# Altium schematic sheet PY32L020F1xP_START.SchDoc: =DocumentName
size A3; Revision: V2.0; SheetNumber: 2; SheetTotal: 2
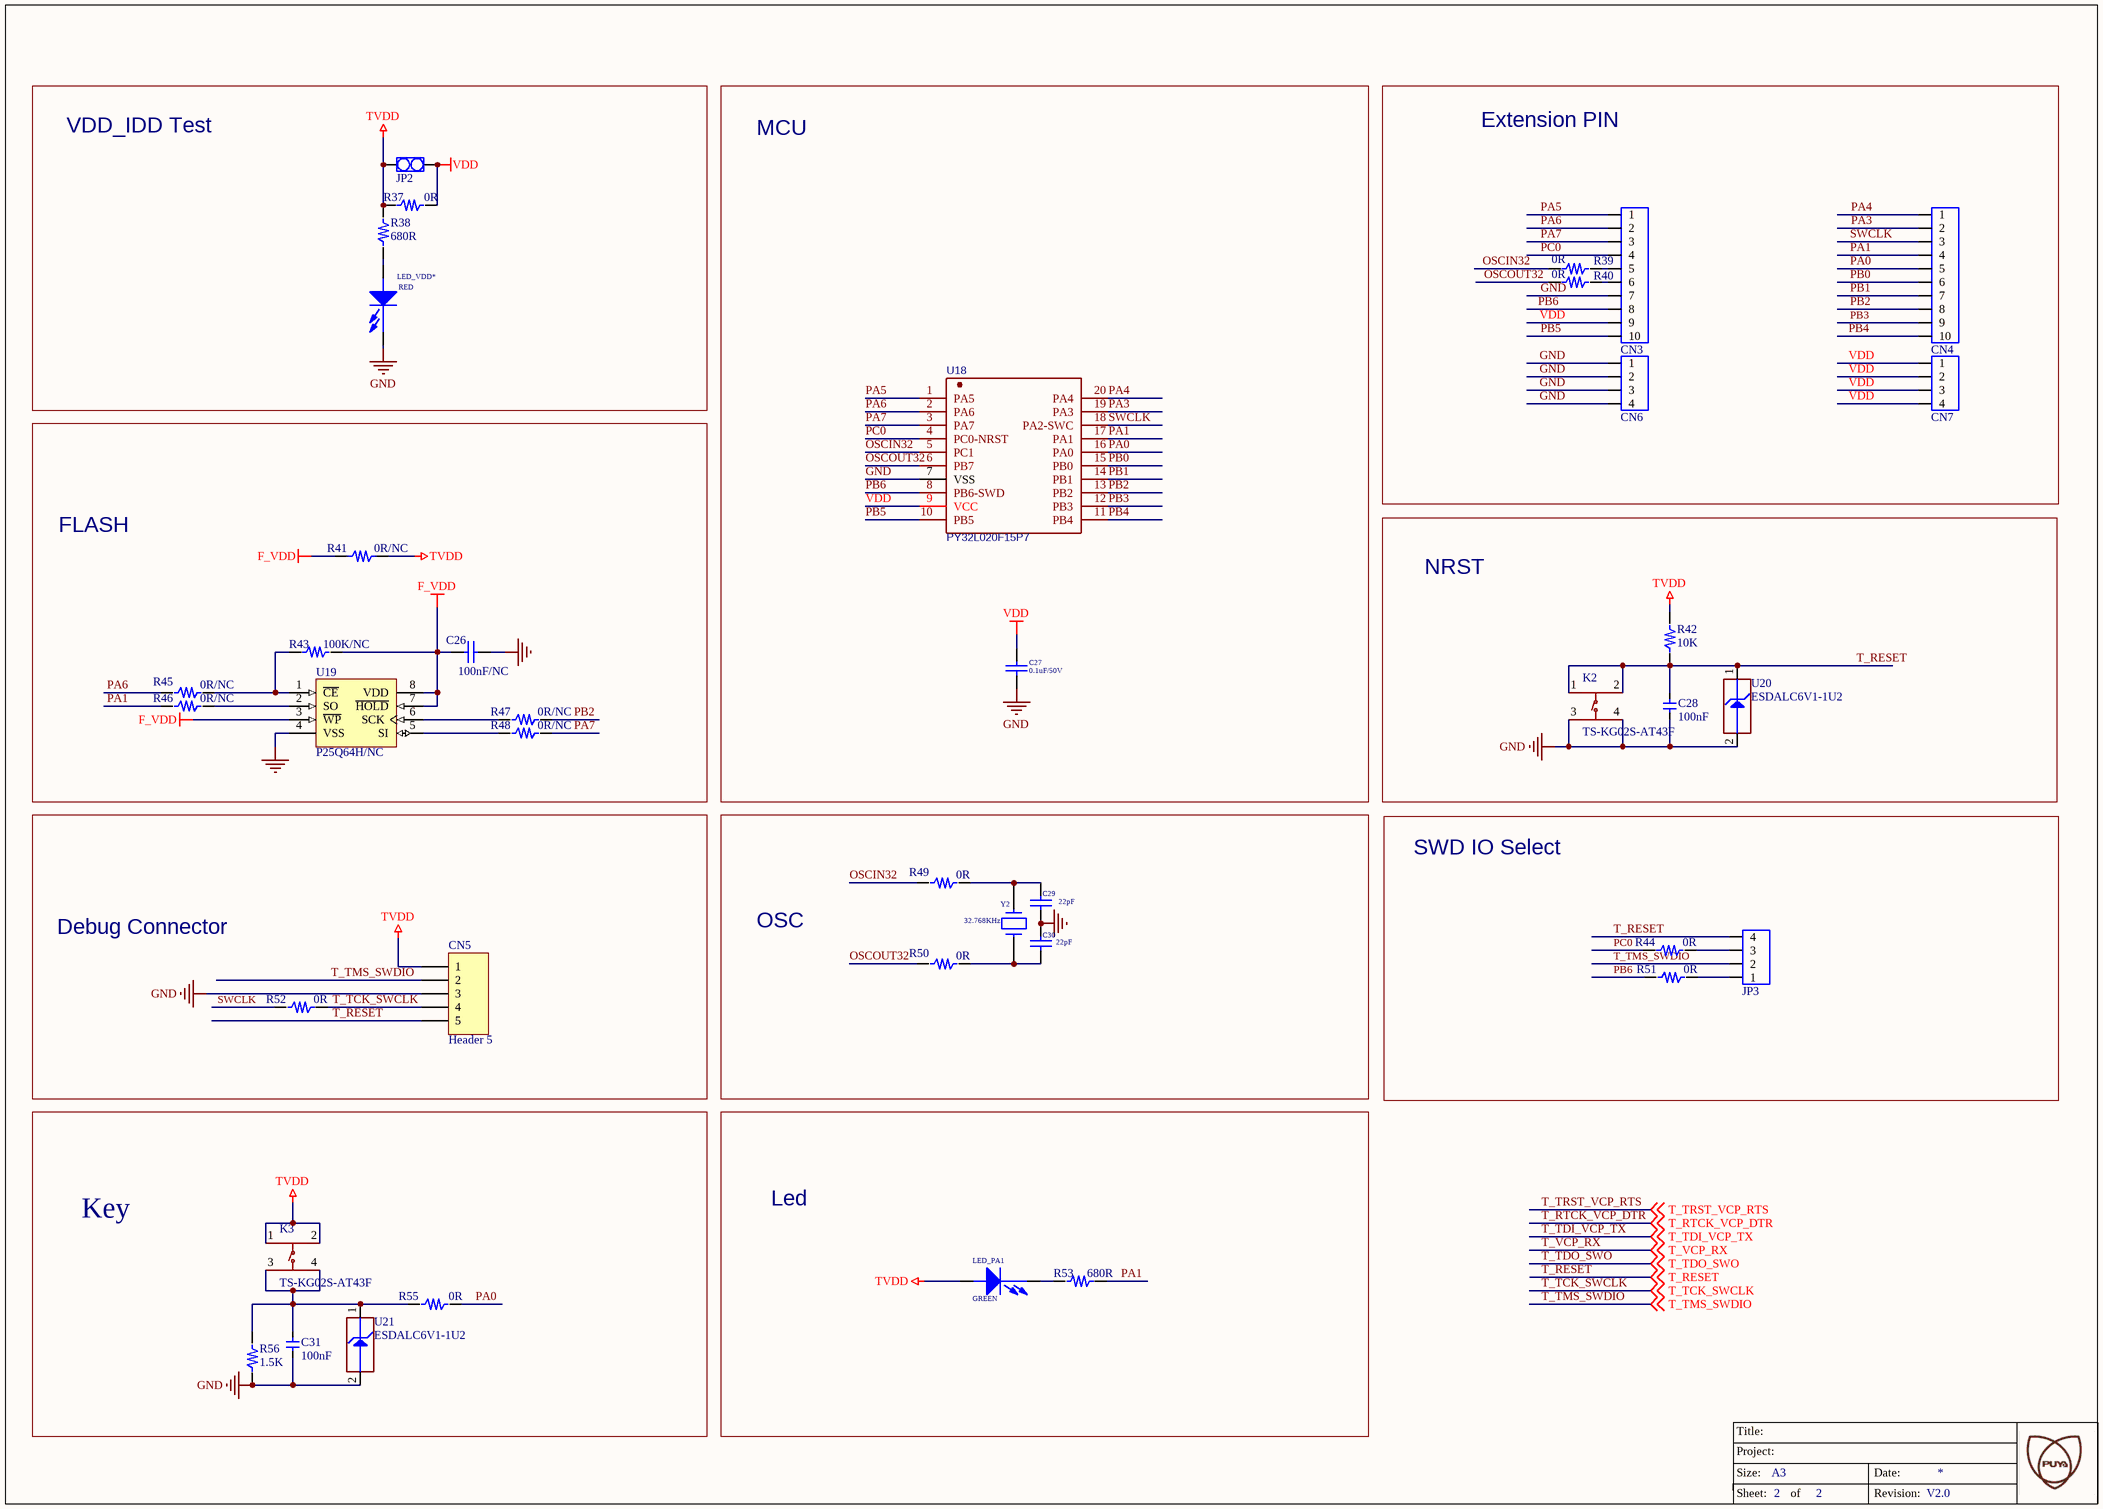
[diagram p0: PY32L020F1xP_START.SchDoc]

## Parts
C26  100nF/NC  [C0603]
C27  0.1uF/50V  [0603C]
C28  100nF  [C0603]
C29  22pF  [0603C]
C30  22pF  [0603C]
C31  100nF  [C0603]
CN3  CON10  [CON10]  (value not drawn)
CN4  CON10  [CON10]  (value not drawn)
CN5  Header 5  [HDR1X5]
CN6  CON4  [CON4]  (value not drawn)
CN7  CON4  [CON4]  (value not drawn)
JP2  CON2  [CON2]  (value not drawn)
JP3  CON4  [CON4]  (value not drawn)
K2  TS-KG02S-AT43F  [SW-SMD_4P-L6.0-W6.0-P4.50-LS8.5]
K3  TS-KG02S-AT43F  [SW-SMD_4P-L6.0-W6.0-P4.50-LS8.5]
LED_PA1  GREEN  [0603_LED]
LED_VDD*  RED  [0603_LED]
R37  0R  [JP2_SMD]
R38  680R  [R0603]
R39  0R  [JP2_SMD]
R40  0R  [JP2_SMD]
R41  0R/NC  [JP2_SMD]
R42  10K  [R0603]
R43  100K/NC  [R0603]
R44  0R  [JP2_SMD]
R45  0R/NC  [JP2_SMD]
R46  0R/NC  [JP2_SMD]
R47  0R/NC  [JP2_SMD]
R48  0R/NC  [JP2_SMD]
R49  0R  [JP2_SMD]
R50  0R  [JP2_SMD]
R51  0R  [JP2_SMD]
R52  0R  [JP2_SMD]
R53  680R  [R0603]
R55  0R  [JP2_SMD]
R56  1.5K  [R0603]
U18  PY32L020F15P7  [TSSOP-20_L6.5-W4.4-P0.65-LS6.4-BL]
U19  P25Q64H/NC  [SOP-8P]
U20  ESDALC6V1-1U2  [ESD_ST0201]
U21  ESDALC6V1-1U2  [ESD_ST0201]
Y2  32.768KHz  [CRYSTAL-SMD_L3.2-W1.5-1]

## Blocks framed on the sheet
VDD_IDD Test: JP2 LED_VDD* R37 R38
MCU: C27 U18
Extension PIN: CN3 CN4 CN6 CN7 R39 R40
FLASH: C26 R41 R43 R45-R48 U19
NRST: C28 K2 R42 U20
Debug Connector: CN5 R52
OSC: C29 C30 R49 R50 Y2
SWD IO Select: JP3 R44 R51
Key: C31 K3 R55 R56 U21
Led: LED_PA1 R53

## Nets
F_VDD: C26.2 R41.2 R43.2 U19.3(~{WP}) U19.7(~{HOLD}) U19.8(VDD)
GND: C26.1 C27.1 C28.1 C29.1 C30.2 C31.1 CN3.7 CN5.3 CN6.1 CN6.2 CN6.3 CN6.4 K2.3 K2.4 LED_VDD*.2(CATHODE) R56.1 U18.7(VSS) U19.4(VSS) U20.2(GND) U21.2(GND)
TVDD: CN5.1 JP2.1 K3.1 K3.2 LED_PA1.1(ANODE) R37.1 R38.2 R41.1 R42.1
VDD: C27.2 CN3.9 CN7.1 CN7.2 CN7.3 CN7.4 JP2.2 R37.2 U18.9(VCC)
OSCIN32: R39.1 R49.2 U18.5(PC1)
OSCOUT32: R40.1 R50.2 U18.6(PB7)
PA0: CN4.5 R55.2 U18.16(PA0)
PA1: CN4.4 R46.2 R53.2 U18.17(PA1)
PA3: CN4.2 U18.19(PA3)
PA4: CN4.1 U18.20(PA4)
PA5: CN3.1 U18.1(PA5)
PA6: CN3.2 R45.2 U18.2(PA6)
PA7: CN3.3 R48.1 U18.3(PA7)
PB0: CN4.6 U18.15(PB0)
PB1: CN4.7 U18.14(PB1)
PB2: CN4.8 R47.1 U18.13(PB2)
PB3: CN4.9 U18.12(PB3)
PB4: CN4.10 U18.11(PB4)
PB5: CN3.10 U18.10(PB5)
PB6: CN3.8 R51.2 U18.8(PB6-SWD)
PC0: CN3.4 R44.2 U18.4(PC0-NRST)
SWCLK: CN4.3 R52.2 U18.18(PA2-SWC)
T_RESET: C28.2 CN5.5 JP3.4 K2.1 K2.2 R42.2 U20.1(IO1) ; off-sheet T_RESET
T_TCK_SWCLK: CN5.4 R52.1 ; off-sheet T_TCK_SWCLK
T_TMS_SWDIO: CN5.2 JP3.2 ; off-sheet T_TMS_SWDIO
NetC29_2: C29.2 R49.1 Y2.1
NetC30_1: C30.1 R50.1 Y2.2
NetC31_2: C31.2 K3.3 K3.4 R55.1 R56.2 U21.1(IO1)
NetCN3_5: CN3.5 R39.2
NetCN3_6: CN3.6 R40.2
NetJP3_1: JP3.1 R51.1
NetJP3_3: JP3.3 R44.1
NetLED_PA1_2: LED_PA1.2(CATHODE) R53.1
NetLED_VDD*_1: LED_VDD*.1(ANODE) R38.1
NetR43_1: R43.1 R45.1 U19.1(~{CE})
NetR46_1: R46.1 U19.2(SO)
NetR47_2: R47.2 U19.6(SCK)
NetR48_2: R48.2 U19.5(SI)

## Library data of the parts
C26 = 贴片高压陶瓷电容: Capacitor (Semiconductor SIM Model); 器件封装(外观): 0603; Value: 104
C27 = CAP: Capacitor; Value: 2.2uF
C28 C31 = C0603: PCB DECAL: 0603
C29 C30 = Cap: Capacitor
CN5 = Header 5: Header, 5-Pin
JP2 = CON2_DIP
K2 K3 = TS-KG02S-AT43F: Manufacturer: HANBO(汉博); Add into BOM: yes; Circuit: 单刀单掷; Actuator Style: 圆形按钮; Operating Force: 250gf; Switch Length: 6mm; Switch Height: 4.3mm; Strike Gundam: 不带; Contact Current: 50mA; Voltage Rating (DC): 12V; Insulation Resistance: 100MΩ; Actuator/Cap Color: 黑色; Pin Style: 鸥翼型
LED_PA1 LED_VDD* = PDI-E803_Dup1
R37-R53 R55 R56 = R0603: PCB DECAL: 0603
U18 = PY32L020F15P7: TSSOP20; BOM_Manufacturer: PUYA(普冉)
U19 = SST25VF010: Value: SST25VF020B; 器件封装(外观): SOP8
U20 U21 = ESDALC6V1-1U2: ESD protection 6V1; Internal_Part_Number: MCD-00170; Part_Type: Diode; Manufacturer: STMICROELECTRONICS; ECCN_US: EAR99; ECCN_EU: NEC; Provided_By: Subcon; Initial_Board_Reference: MB1274
Y2 = CRYSTAL_1: Crystal; Value: X503225MSB2GI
